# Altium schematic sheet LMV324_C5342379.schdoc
size 127 x 101 mm
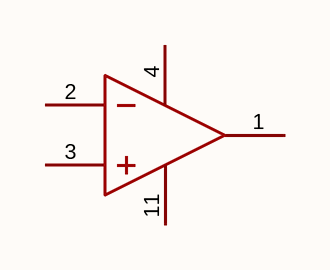
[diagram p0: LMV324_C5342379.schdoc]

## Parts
U?  lmv324_c5342379  [SOIC-14_L8.7-W3.9-P1.27-LS6.0-BL]  (value not drawn)  (part A of 4)

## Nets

Not connected (* = marked no-connect by the designer): U? 1(OUTA) 2(INA−) 3(INA+) 4(VDD) 11(VSS)

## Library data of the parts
U? = lmv324_c5342379: 放大器数:2;轨到轨:轨到轨输入,轨到轨输出;增益带宽积(GBW):1MHz;输入失调电压(Vos):5mV;压摆率(SR):600V/ms;输入偏置电流(Ib):10pA;; Manufacturer: TECH PUBLIC(台舟); ManufacturerPart: LMV324; AddInBom: yes; ModelId: 8dbf5b715d42428c85558507ae5a252b; ModelName: SOIC-14_L8.6-W3.9-H1.8-LS6.0-P1.27; ModelTransform: 338.583,236.22,0,0,0,0,0,0.001,0; Number of Channels: 2; Maximum Power Supply Range (Vdd-Vss): 7V; Gain Bandwidth Product: 1MHz; Vos - Input Offset Voltage: 5mV; Input Offset Voltage Drift(Vos TC): 2uV/℃; Ib - Input Bias Current: 10pA; Input Voltage Noise Density: 20nV/√Hz@10kHz; Common Mode Rejection Ratio(CMRR): 80dB; Quiescent Current: 40uA; Output Current: 20mA; Single supply: 2.2V~5.5V; Dual Supply: 1.1V~2.75V；-2.75V~-1.1V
